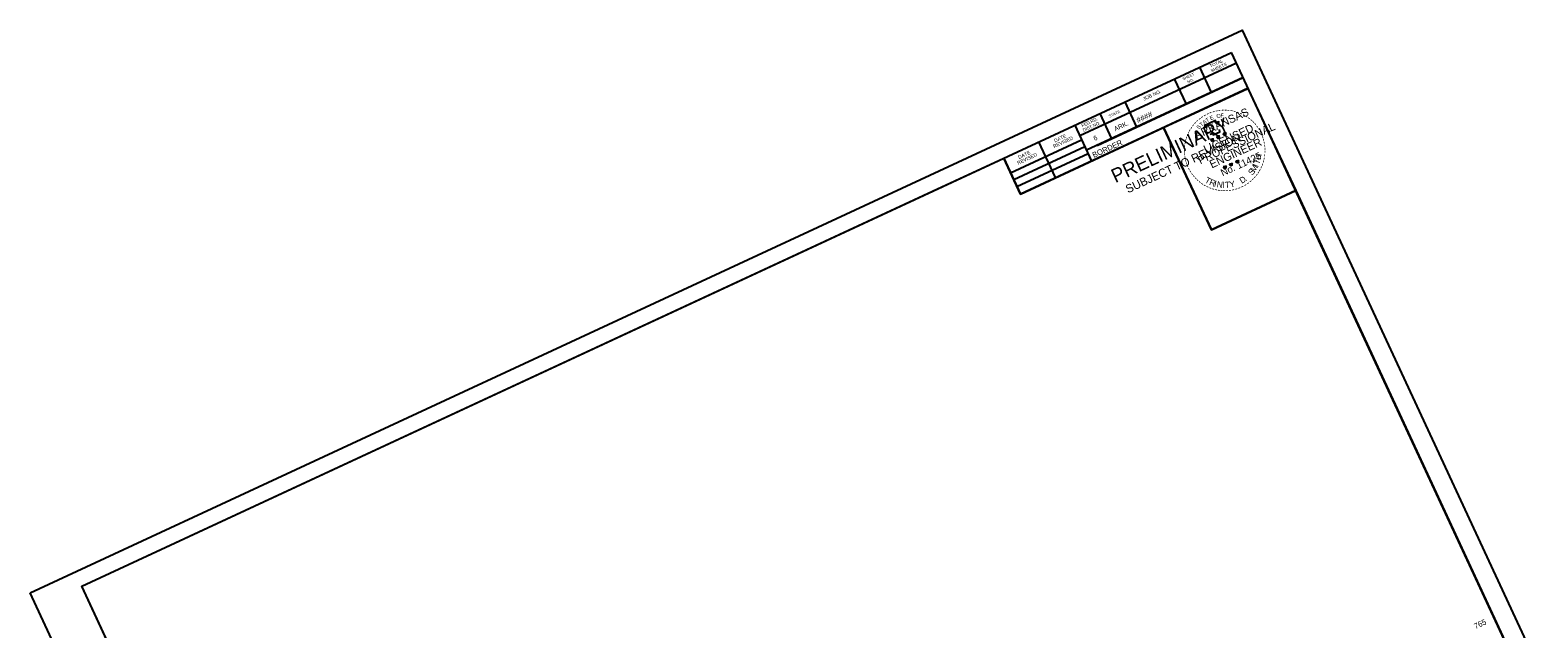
# Model space of a CAD drawing. Extents: x 1354696 to 1366163, y 660729 to 670380.
# Drawn here: x 1354695.9 to 1355072, y 665250.9 to 665400.3 of the extents above; entities that cross this region are included whole.
import ezdxf

# ---------------------------------------------------------------- set-up
doc = ezdxf.new("R2010")
doc.units = 0
for name, color, linetype in [('R_Axis Annot', 7, 'Continuous'), ('R_Border', 7, 'Continuous'), ('R_Border PE', 7, 'Continuous'), ('R_Border Prem', 7, 'Continuous'), ('R_No Plot', 7, 'Continuous')]:
    doc.layers.add(name, color=color, linetype=linetype)

msp = doc.modelspace()

# ---------------------------------------------------------------- linework, layer by layer
at = {"layer": 'R_Border'}
for p, q in [((1354708.8, 665261.62), (1354995.58, 665394.76)), ((1355082.1, 665208.41), (1354995.58, 665394.76)), ((1354996.82, 665392.09), (1354957.72, 665373.95)), ((1354987.6, 665391.06), (1354990.52, 665384.76)), ((1354996.81, 665392.11), (1354996.81, 665392.11)), ((1354998.5, 665388.47), (1354959.41, 665370.32)), ((1354962.09, 665371.56), (1354998.5, 665388.47)), ((1354981.3, 665388.13), (1354984.22, 665381.84)), ((1354999.74, 665385.8), (1354942.92, 665359.42)), ((1354962.69, 665379.49), (1354965.61, 665373.2)), ((1354968.99, 665382.41), (1354971.91, 665376.12)), ((1354956.49, 665376.61), (1354960.65, 665367.65)), ((1354940.46, 665364.74), (1354958.18, 665372.97)), ((1354951.7, 665363.5), (1354947.54, 665372.46)), ((1354942.92, 665359.42), (1354938.76, 665368.38)), ((1354941.24, 665363.05), (1354958.96, 665371.28)), ((1354942.06, 665361.29), (1354959.78, 665369.52)), ((1354847.25, 665325.61), (1354847.25, 665325.61)), ((1354847.25, 665325.61), (1354847.25, 665325.61)), ((1354795.32, 665075.26), (1354708.8, 665261.62))]:
    msp.add_line(p, q, dxfattribs=at)
at = {"layer": 'R_Border PE'}
for p, q in [((1354990.38, 665372.92), (1354990.63, 665372.98)), ((1354990.38, 665372.92), (1354990.74, 665372.96)), ((1354990.38, 665372.92), (1354990.65, 665372.9)), ((1354990.74, 665372.96), (1354990.59, 665373.29)), ((1354990.59, 665373.29), (1354990.74, 665373.09)), ((1354990.59, 665373.29), (1354990.66, 665373.05)), ((1354990.67, 665372.6), (1354990.74, 665372.96)), ((1354990.67, 665372.6), (1354990.77, 665372.89)), ((1354990.67, 665372.6), (1354990.68, 665372.88)), ((1354991.01, 665373.21), (1354990.74, 665372.96)), ((1354991.06, 665372.78), (1354990.74, 665372.96)), ((1354991.01, 665373.21), (1354990.77, 665373.04)), ((1354991.06, 665372.78), (1354990.78, 665372.89)), ((1354991.06, 665372.78), (1354990.81, 665372.99)), ((1354991.01, 665373.21), (1354990.87, 665373.03)), ((1354991.89, 665373.62), (1354992.14, 665373.68)), ((1354991.89, 665373.62), (1354992.26, 665373.67)), ((1354991.89, 665373.62), (1354992.16, 665373.61)), ((1354992.26, 665373.67), (1354992.1, 665374)), ((1354992.1, 665374), (1354992.25, 665373.79)), ((1354992.1, 665374), (1354992.17, 665373.75)), ((1354992.19, 665373.3), (1354992.26, 665373.67)), ((1354992.19, 665373.3), (1354992.29, 665373.59)), ((1354992.19, 665373.3), (1354992.2, 665373.58)), ((1354992.53, 665373.91), (1354992.26, 665373.67)), ((1354992.58, 665373.49), (1354992.26, 665373.67)), ((1354992.53, 665373.91), (1354992.29, 665373.75)), ((1354992.58, 665373.49), (1354992.29, 665373.59)), ((1354992.58, 665373.49), (1354992.33, 665373.69)), ((1354992.53, 665373.91), (1354992.38, 665373.73)), ((1354993.5, 665374.35), (1354993.75, 665374.42)), ((1354993.5, 665374.35), (1354993.86, 665374.4)), ((1354993.5, 665374.35), (1354993.77, 665374.34)), ((1354993.86, 665374.4), (1354993.71, 665374.73)), ((1354993.71, 665374.73), (1354993.86, 665374.52)), ((1354993.71, 665374.73), (1354993.78, 665374.48)), ((1354993.79, 665374.04), (1354993.86, 665374.4)), ((1354993.79, 665374.04), (1354993.89, 665374.32)), ((1354993.79, 665374.04), (1354993.8, 665374.31)), ((1354994.13, 665374.64), (1354993.86, 665374.4)), ((1354994.18, 665374.22), (1354993.86, 665374.4)), ((1354994.13, 665374.64), (1354993.89, 665374.48)), ((1354994.18, 665374.22), (1354993.9, 665374.32)), ((1354994.18, 665374.22), (1354993.93, 665374.42)), ((1354994.13, 665374.64), (1354993.99, 665374.47)), ((1354993.56, 665366.05), (1354993.81, 665366.11)), ((1354993.56, 665366.05), (1354993.93, 665366.09)), ((1354993.56, 665366.05), (1354993.83, 665366.03)), ((1354993.93, 665366.09), (1354993.77, 665366.42)), ((1354993.77, 665366.42), (1354993.92, 665366.22)), ((1354993.77, 665366.42), (1354993.84, 665366.18)), ((1354993.86, 665365.73), (1354993.93, 665366.09)), ((1354993.86, 665365.73), (1354993.96, 665366.02)), ((1354993.86, 665365.73), (1354993.87, 665366.01)), ((1354994.2, 665366.34), (1354993.93, 665366.09)), ((1354994.25, 665365.91), (1354993.93, 665366.09)), ((1354994.2, 665366.34), (1354993.96, 665366.17)), ((1354994.25, 665365.91), (1354993.96, 665366.02)), ((1354994.25, 665365.91), (1354994, 665366.12)), ((1354994.2, 665366.34), (1354994.05, 665366.16)), ((1354995.08, 665366.75), (1354995.33, 665366.81)), ((1354995.08, 665366.75), (1354995.44, 665366.79)), ((1354995.08, 665366.75), (1354995.34, 665366.74)), ((1354995.44, 665366.79), (1354995.29, 665367.13)), ((1354995.29, 665367.13), (1354995.44, 665366.92)), ((1354995.29, 665367.13), (1354995.36, 665366.88)), ((1354995.37, 665366.43), (1354995.44, 665366.79)), ((1354995.37, 665366.43), (1354995.47, 665366.72)), ((1354995.37, 665366.43), (1354995.38, 665366.71)), ((1354995.71, 665367.04), (1354995.44, 665366.79)), ((1354995.76, 665366.61), (1354995.44, 665366.79)), ((1354995.71, 665367.04), (1354995.47, 665366.88)), ((1354995.76, 665366.61), (1354995.47, 665366.72)), ((1354995.76, 665366.61), (1354995.51, 665366.82)), ((1354995.71, 665367.04), (1354995.57, 665366.86)), ((1354996.69, 665367.48), (1354996.93, 665367.55)), ((1354996.69, 665367.48), (1354997.05, 665367.53)), ((1354996.69, 665367.48), (1354996.95, 665367.47)), ((1354997.05, 665367.53), (1354996.9, 665367.86)), ((1354996.9, 665367.86), (1354997.04, 665367.65)), ((1354996.9, 665367.86), (1354996.96, 665367.61)), ((1354996.98, 665367.17), (1354997.05, 665367.53)), ((1354996.98, 665367.17), (1354997.08, 665367.46)), ((1354996.98, 665367.17), (1354996.99, 665367.44)), ((1354997.32, 665367.78), (1354997.05, 665367.53)), ((1354997.37, 665367.35), (1354997.05, 665367.53)), ((1354997.32, 665367.78), (1354997.08, 665367.61)), ((1354997.37, 665367.35), (1354997.08, 665367.45)), ((1354997.37, 665367.35), (1354997.12, 665367.56)), ((1354997.32, 665367.78), (1354997.17, 665367.6))]:
    msp.add_line(p, q, dxfattribs=at)
for points in [[(1354992.36, 665377.09), (1354992.37, 665377.41), (1354991.75, 665377.1), (1354991.61, 665377.76), (1354988.78, 665376.45)], [(1354988.78, 665376.45), (1354989.38, 665375.81)], [(1354990.25, 665374.46), (1354990.29, 665374.38), (1354990.81, 665374.6), (1354990.96, 665374.15), (1354992.65, 665374.94), (1354992.61, 665375.51)], [(1354990.59, 665373.29), (1354991.06, 665372.78), (1354990.38, 665372.92), (1354991.01, 665373.21), (1354990.67, 665372.6), (1354990.59, 665373.29)], [(1354992.1, 665374), (1354992.58, 665373.49), (1354991.89, 665373.62), (1354992.53, 665373.91), (1354992.19, 665373.3), (1354992.1, 665374)], [(1354993.71, 665374.73), (1354994.18, 665374.22), (1354993.5, 665374.35), (1354994.13, 665374.64), (1354993.79, 665374.04), (1354993.71, 665374.73)], [(1354993.77, 665366.42), (1354994.25, 665365.91), (1354993.56, 665366.05), (1354994.2, 665366.34), (1354993.86, 665365.73), (1354993.77, 665366.42)], [(1354995.29, 665367.13), (1354995.76, 665366.61), (1354995.08, 665366.75), (1354995.71, 665367.04), (1354995.37, 665366.43), (1354995.29, 665367.13)], [(1354996.9, 665367.86), (1354997.37, 665367.35), (1354996.69, 665367.48), (1354997.32, 665367.78), (1354996.98, 665367.17), (1354996.9, 665367.86)]]:
    msp.add_lwpolyline(points, dxfattribs=at)
for centre, radius in [((1354990.74, 665372.96), 0.172), ((1354990.74, 665372.96), 0.145), ((1354990.74, 665372.96), 0.116), ((1354990.74, 665372.96), 0.0991), ((1354990.74, 665372.96), 0.0747), ((1354990.74, 665372.96), 0.0495), ((1354990.74, 665372.96), 0.0296), ((1354992.26, 665373.66), 0.172), ((1354992.26, 665373.66), 0.145), ((1354992.26, 665373.66), 0.116), ((1354992.26, 665373.66), 0.0991), ((1354992.26, 665373.66), 0.0747), ((1354992.26, 665373.66), 0.0495), ((1354992.26, 665373.66), 0.0296), ((1354993.86, 665374.4), 0.172), ((1354993.86, 665374.4), 0.145), ((1354993.86, 665374.4), 0.116), ((1354993.86, 665374.4), 0.0991), ((1354993.86, 665374.4), 0.0747), ((1354993.86, 665374.4), 0.0495), ((1354993.86, 665374.4), 0.0296), ((1354993.93, 665366.09), 0.172), ((1354993.93, 665366.09), 0.145), ((1354993.93, 665366.09), 0.116), ((1354993.93, 665366.09), 0.0991), ((1354993.93, 665366.09), 0.0747), ((1354993.93, 665366.09), 0.0495), ((1354993.93, 665366.09), 0.0296), ((1354995.44, 665366.79), 0.172), ((1354995.44, 665366.79), 0.145), ((1354995.44, 665366.79), 0.116), ((1354995.44, 665366.79), 0.0991), ((1354995.44, 665366.79), 0.0747), ((1354995.44, 665366.79), 0.0495), ((1354995.44, 665366.79), 0.0296), ((1354997.05, 665367.53), 0.172), ((1354997.05, 665367.53), 0.145), ((1354997.05, 665367.53), 0.116), ((1354997.05, 665367.53), 0.0991), ((1354997.05, 665367.53), 0.0747), ((1354997.05, 665367.53), 0.0495), ((1354997.05, 665367.53), 0.0296)]:
    msp.add_circle(centre, radius, dxfattribs=at)
at = {"layer": 'R_No Plot'}
for p, q in [((1354695.91, 665259.93), (1354998.25, 665400.29)), ((1354987.46, 665355.34), (1354987.46, 665355.34))]:
    msp.add_line(p, q, dxfattribs=at)
for points in [[(1354695.91, 665259.92), (1354998.25, 665400.29), (1355088.09, 665206.79), (1354785.74, 665066.42)], [(1354978.58, 665375.98), (1354999.63, 665385.75), (1355011.6, 665360.26), (1354990.55, 665350.49)], [(1354920.97, 665360.12), (1354938.76, 665368.38), (1354942.92, 665359.42), (1354957.54, 665366.21), (1354978.58, 665375.98), (1354990.55, 665350.49), (1355011.6, 665360.26), (1355082.1, 665208.41), (1354795.32, 665075.26), (1354708.8, 665261.62)]]:
    msp.add_lwpolyline(points, close=True, dxfattribs=at)

# ---------------------------------------------------------------- texts
at = {"layer": 'R_Axis Annot'}
msp.add_text('765', height=1.4, rotation=24.9042, dxfattribs=at).set_placement((1355056.46, 665250.86))
at = {"layer": 'R_Border'}
for s, height, p in [('TOTAL', 0.782, (1354990.35, 665390.92)), ('SHEETS', 0.782, (1354990.59, 665389.73)), ('SHEET', 0.684, (1354983.53, 665387.76)), ('NO.', 0.684, (1354984.73, 665387.01)), ('JOB NO.', 0.879, (1354973.72, 665382.67)), ('STATE', 0.684, (1354965.11, 665378.46)), ('####', 1.4, (1354972.23, 665377.08)), ('FED.RD.', 0.782, (1354958.37, 665376.07)), ('DIST.NO.', 0.782, (1354958.68, 665374.92)), ('ARK.', 1.172, (1354966.59, 665375.04)), ('REVISED', 0.879, (1354951.31, 665370.85)), ('DATE', 0.879, (1354951.52, 665372.25)), ('BORDER', 1.4, (1354961.25, 665368.4)), ('6', 1.17, (1354961.45, 665372.66)), ('REVISED', 0.879, (1354942.37, 665366.7)), ('DATE', 0.879, (1354942.58, 665368.1))]:
    msp.add_text(s, height=height, rotation=24.9042, dxfattribs=at).set_placement(p)
at = {"layer": 'R_Border PE'}
for s, height, rotation, p in [('ARKANSAS', 2, 24.9042, (1354986.89, 665373.05)), ('-', 1.6, 30.801, (1354988.91, 665378.32)), ('-', 1.6, 25.0904, (1354989.58, 665378.71)), ('-', 1.6, 22.6472, (1354990.24, 665379)), ('-', 1.6, 17.0659, (1354990.94, 665379.26)), ('-', 1.6, 12.1091, (1354991.64, 665379.46)), ('O', 1, 15.3557, (1354991.96, 665378.28)), ('-', 1.6, 7.2404, (1354992.28, 665379.59)), ('F', 1, 4.9748, (1354992.92, 665378.48)), ('-', 1.6, 2.7593, (1354993.05, 665379.7)), ('-', 1.6, 359.0253, (1354993.73, 665379.72)), ('-', 1.6, 354.5451, (1354994.38, 665379.7)), ('-', 1.6, 350.7668, (1354995.11, 665379.65)), ('-', 1.6, 345.4339, (1354995.84, 665379.52)), ('-', 1.6, 340.4828, (1354996.59, 665379.33)), ('-', 1.6, 334.7839, (1354997.34, 665379.07)), ('-', 1.6, 331.5563, (1354998.07, 665378.74)), ('-', 1.6, 61.1359, (1354985.53, 665374.69)), ('-', 1.6, 58.9677, (1354985.89, 665375.29)), ('-', 1.6, 53.696, (1354986.27, 665375.88)), ('-', 1.6, 49.2114, (1354986.71, 665376.43)), ('-', 1.6, 44.0802, (1354987.17, 665376.95)), ('S', 1, 46.4982, (1354987.43, 665375.47)), ('PROFESSIONAL', 2, 24.9042, (1354987.79, 665366.79)), ('-', 1.6, 38.5343, (1354987.75, 665377.48)), ('T', 1, 41.3078, (1354988.12, 665376.15)), ('-', 1.6, 35.1235, (1354988.3, 665377.91)), ('A', 1, 36.1173, (1354988.76, 665376.73)), ('LICENSED', 2, 24.9042, (1354989.18, 665369.54)), ('T', 1, 30.9269, (1354989.46, 665377.23)), ('E', 1, 25.7365, (1354990.42, 665377.8)), ('-', 1.4, 328.5795, (1354998.75, 665378.43)), ('-', 1.6, 324.5725, (1354999.29, 665378.02)), ('-', 1.6, 319.567, (1354999.85, 665377.6)), ('-', 1.6, 315.477, (1355000.32, 665377.18)), ('-', 1.6, 310.0274, (1355000.78, 665376.76)), ('-', 1.6, 305.4535, (1355001.27, 665376.17)), ('-', 1.6, 301.5003, (1355001.74, 665375.54)), ('-', 1.6, 82.9748, (1354984.46, 665371.05)), ('-', 1.6, 79.1366, (1354984.54, 665371.67)), ('-', 1.6, 75.5183, (1354984.67, 665372.35)), ('-', 1.6, 73.3272, (1354984.83, 665372.97)), ('-', 1.6, 67.8664, (1354985.04, 665373.59)), ('-', 1.6, 63.8548, (1354985.25, 665374.15)), ('ENGINEER', 2, 24.9042, (1354990.66, 665365.78)), ('DWB', 0.01, 24.9042, (1354990.73, 665372.95)), ('DWB', 0.01, 24.9042, (1354992.25, 665373.65)), ('DWB', 0.01, 24.9042, (1354993.85, 665374.39)), ('-', 1.6, 299.2343, (1355002.1, 665374.91)), ('-', 1.6, 294.8448, (1355002.4, 665374.35)), ('-', 1.6, 288.4214, (1355002.66, 665373.74)), ('-', 1.6, 285.8995, (1355002.87, 665373.12)), ('-', 1.6, 280.6668, (1355003.06, 665372.45)), ('-', 1.6, 277.7723, (1355003.2, 665371.72)), ('-', 1.6, 92.6784, (1354984.46, 665369.7)), ('-', 1.6, 87.7755, (1354984.44, 665370.36)), ('-', 1.6, 97.2986, (1354984.53, 665369.04)), ('-', 1.6, 100.3651, (1354984.65, 665368.31)), ('-', 1.6, 106.1054, (1354984.83, 665367.6)), ('No. 11425', 1.757, 24.9042, (1354993.38, 665363.79)), ('T', 1.54, 71.5486, (1355002.47, 665366.67)), ('H', 1.54, 79.513, (1355002.88, 665367.9)), ('-', 1.6, 258.7494, (1355003.18, 665368.73)), ('-', 1.6, 263.9754, (1355003.27, 665369.49)), ('-', 1.6, 272.7928, (1355003.28, 665371.02)), ('-', 1.6, 269.5239, (1355003.31, 665370.34)), ('-', 1.6, 110.0905, (1354985.05, 665366.94)), ('-', 1.6, 113.9664, (1354985.32, 665366.3)), ('-', 1.6, 119.1, (1354985.66, 665365.66)), ('-', 1.6, 123.8521, (1354986.01, 665365.08)), ('-', 1.6, 126.6191, (1354986.44, 665364.47)), ('DWB', 0.01, 24.9042, (1354993.92, 665366.08)), ('DWB', 0.01, 24.9042, (1354995.43, 665366.78)), ('DWB', 0.01, 24.9042, (1354997.04, 665367.52)), ('S', 1.54, 51.8354, (1355000.76, 665363.97)), ('M', 1.54, 57.5605, (1355001.35, 665364.69)), ('I', 1.54, 67.0178, (1355002.16, 665366)), ('-', 1.6, 232.261, (1355001.59, 665364.86)), ('-', 1.6, 237.1533, (1355001.95, 665365.41)), ('-', 1.6, 240.6405, (1355002.27, 665365.98)), ('-', 1.6, 245.9893, (1355002.57, 665366.64)), ('-', 1.6, 250.6695, (1355002.83, 665367.32)), ('-', 1.6, 256.1579, (1355003.02, 665368.04)), ('-', 1.6, 130.362, (1354986.84, 665364)), ('-', 1.6, 133.9916, (1354987.3, 665363.52)), ('-', 1.6, 138.9685, (1354987.78, 665363.09)), ('-', 1.6, 140.633, (1354988.31, 665362.65)), ('-', 1.6, 145.3513, (1354988.88, 665362.27)), ('-', 1.6, 150.7976, (1354989.49, 665361.93)), ('T', 1.54, 330.9447, (1354988.76, 665362.41)), ('-', 1.6, 155.6223, (1354990.14, 665361.63)), ('-', 1.6, 159.128, (1354990.84, 665361.35)), ('R', 1.54, 338.9091, (1354989.89, 665361.78)), ('-', 1.6, 163.838, (1354991.51, 665361.15)), ('I', 1.54, 346.8735, (1354991.1, 665361.31)), ('-', 1.6, 169.5505, (1354992.18, 665361.02)), ('N', 1.54, 351.4044, (1354991.81, 665361.13)), ('-', 1.6, 172.9939, (1354992.85, 665360.92)), ('I', 1.54, 0.2645, (1354993.24, 665360.92)), ('T', 1.54, 4.7953, (1354993.98, 665360.9)), ('-', 1.6, 187.7024, (1354995.47, 665360.99)), ('Y', 1.54, 12.7597, (1354995.27, 665361.01)), ('-', 1.6, 192.4597, (1354996.19, 665361.14)), ('-', 1.6, 198.0196, (1354996.94, 665361.37)), ('-', 1.6, 201.4224, (1354997.64, 665361.63)), ('D', 1.54, 31.3011, (1354998.13, 665361.94)), ('-', 1.6, 206.4959, (1354998.31, 665361.97)), ('-', 1.6, 210.7208, (1354999.01, 665362.37)), ('.', 1.54, 38.6683, (1354999.15, 665362.56)), ('-', 1.6, 216.1899, (1354999.62, 665362.8)), ('-', 1.6, 220.3785, (1355000.2, 665363.29)), ('-', 1.6, 225.6226, (1355000.71, 665363.8)), ('-', 1.6, 229.1558, (1355001.16, 665364.3)), ('-', 1.6, 176.4746, (1354993.51, 665360.87)), ('-', 1.6, 179.5044, (1354994.09, 665360.86)), ('-', 1.6, 183.4654, (1354994.76, 665360.89))]:
    msp.add_text(s, height=height, rotation=rotation, dxfattribs=at).set_placement(p)
at = {"layer": 'R_Border Prem'}
for s, height, p in [('PRELIMINARY', 3.5, (1354966.59, 665362.1)), ('SUBJECT TO REVISION', 2.0751, (1354969.76, 665359.57)), ('DWB', 0.01, (1354966.49, 665364.09))]:
    msp.add_text(s, height=height, rotation=24.9042, dxfattribs=at).set_placement(p)

doc.saveas('drawing.dxf')
